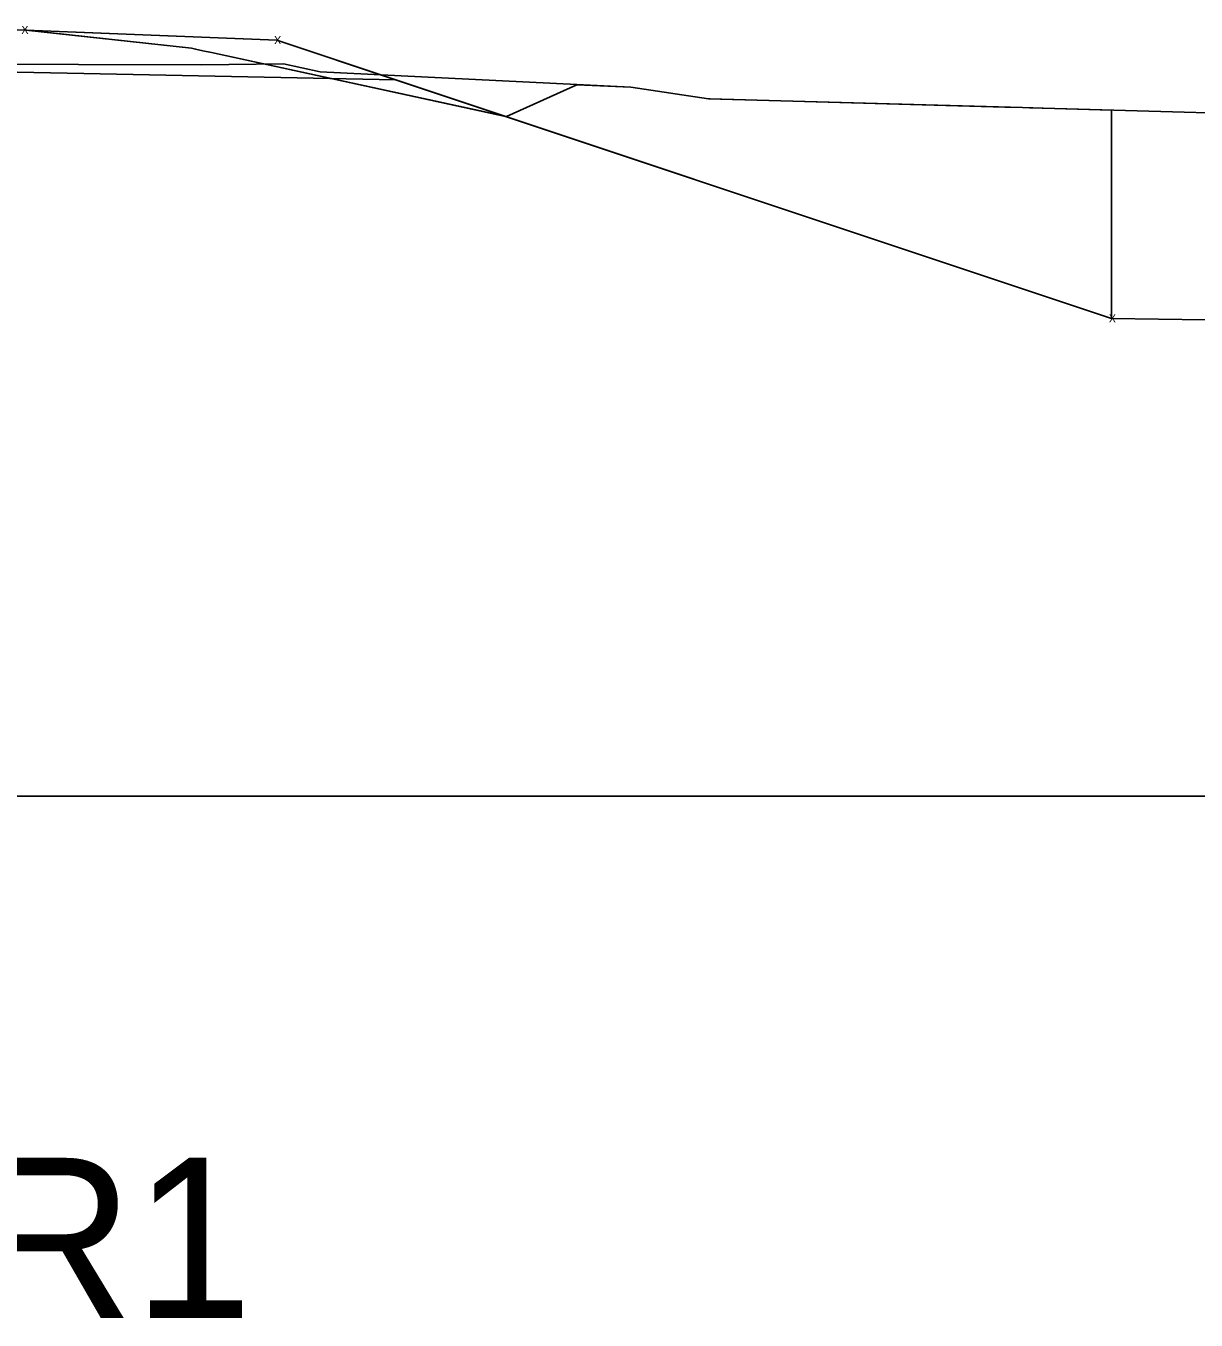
# Model space of a CAD drawing. Extents: x -26 to 303, y -16 to 6048.
# Drawn here: x 165.76 to 200.87, y 3484.28 to 3523.1 of the extents above; entities that cross this region are included whole.
import ezdxf

# ---------------------------------------------------------------- set-up
doc = ezdxf.new("R2010")
doc.units = 0
for name, color, linetype in [('CONST_DCH', 7, 'Continuous'), ('Draft_XS_Text', 7, 'Continuous'), ('DTM_TEMP_DROP', 7, 'Continuous'), ('DTM_X_GROUND', 7, 'Continuous'), ('X_PROFILES_1', 7, 'Continuous'), ('XS_CELL', 7, 'Continuous'), ('XS_M_SHAPES_EARTHWORK', 7, 'Continuous'), ('XS_P_GROUND', 7, 'Continuous'), ('XS_P_NULL_POINT', 7, 'Continuous'), ('XS_P_SHOULDER', 7, 'Continuous'), ('XS_P_SUBGRADE_GRANULAR', 7, 'Continuous')]:
    doc.layers.add(name, color=color, linetype=linetype)

msp = doc.modelspace()

# ---------------------------------------------------------------- linework, layer by layer
at = {"layer": 'DTM_X_GROUND'}
for points in [[(165.707, 3522.982), (170.73, 3522.431), (170.853, 3522.405), (171.073, 3522.357), (171.337, 3522.3), (180.188, 3520.379), (182.289, 3521.329), (183.914, 3521.26), (186.242, 3520.911), (186.296, 3520.916), (195.137, 3520.664), (195.662, 3520.649), (195.878, 3520.644), (195.969, 3520.641), (196.254, 3520.635), (196.27, 3520.634), (196.283, 3520.634), (205.45, 3520.374)], [(96.02, 3516.501), (102.4, 3517.392), (107.037, 3518.039), (115.756, 3518.481), (127.327, 3521.698), (129.588, 3521.745), (130.655, 3521.767), (132.204, 3521.843), (139.271, 3521.919), (150.5, 3522.03), (159.946, 3521.966), (171.035, 3521.93), (173.489, 3521.967), (174.598, 3521.727), (182.289, 3521.341), (183.914, 3521.26), (186.242, 3520.917), (195.662, 3520.649), (196.283, 3520.634), (205.45, 3520.374)]]:
    msp.add_lwpolyline(points, dxfattribs=at)
at = {"layer": 'XS_CELL'}
msp.add_line((150, 3500), (300, 3500), dxfattribs=at)
at = {"layer": 'XS_M_SHAPES_EARTHWORK'}
for points in [[(165.764, 3522.975), (170.73, 3522.431), (170.853, 3522.405), (171.073, 3522.357), (171.337, 3522.3), (180.154, 3520.386), (176.849, 3521.488), (173.29, 3522.674)], [(180.154, 3520.386), (180.188, 3520.379), (182.289, 3521.329), (183.914, 3521.26), (186.242, 3520.911), (186.296, 3520.916), (195.137, 3520.664), (195.662, 3520.649), (195.878, 3520.644), (195.969, 3520.641), (196.254, 3520.635), (196.27, 3520.634), (196.283, 3520.634), (198.332, 3520.576), (198.332, 3514.327)]]:
    msp.add_lwpolyline(points, close=True, dxfattribs=at)
at = {"layer": 'XS_P_GROUND'}
for points in [[(173.29, 3522.674), (198.332, 3514.327)], [(198.332, 3514.327), (201.155, 3514.285)]]:
    msp.add_lwpolyline(points, dxfattribs=at)
at = {"layer": 'XS_P_SHOULDER'}
msp.add_lwpolyline([(165.506, 3522.986), (173.29, 3522.674)], dxfattribs=at)
at = {"layer": 'XS_P_SUBGRADE_GRANULAR'}
msp.add_lwpolyline([(165.506, 3521.715), (167.506, 3521.675), (176.849, 3521.488)], dxfattribs=at)
msp.add_lwpolyline([(165.506, 3521.715), (167.506, 3521.675), (176.849, 3521.488)], dxfattribs=at)

# ---------------------------------------------------------------- texts
at = {"layer": 'CONST_DCH'}
msp.add_text('X', height=0.24, dxfattribs=at).set_placement((198.254, 3514.207))
at = {"layer": 'Draft_XS_Text'}
msp.add_text('Sta. 165+00.0000 R1', height=4.8, dxfattribs=at).set_placement((111.716, 3484.35))
at = {"layer": 'DTM_TEMP_DROP'}
msp.add_text('X', height=0.24, dxfattribs=at).set_placement((198.254, 3514.207))
at = {"layer": 'X_PROFILES_1'}
msp.add_text('X', height=0.24, dxfattribs=at).set_placement((173.211, 3522.554))
at = {"layer": 'XS_P_NULL_POINT'}
msp.add_text('X', height=0.24, dxfattribs=at).set_placement((165.628, 3522.862))

doc.saveas('drawing.dxf')
